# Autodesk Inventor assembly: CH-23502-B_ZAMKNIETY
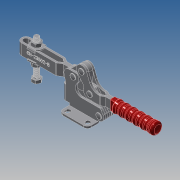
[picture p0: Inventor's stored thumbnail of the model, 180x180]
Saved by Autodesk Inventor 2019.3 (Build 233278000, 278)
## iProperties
Company: ·L?¤¤?
Created: 2010-06
Part Number: CH-23502-B_ZAMKNIETY
Material: Ogólny
Description: STEP AP203
Document SubType Name: Assembly
Designer: CADENGINEERING4
Sending System: SolidWorks 2005179
Preprocessor: SwSTEP 2.0
Title: CH-23502-B.STEP
Author: ·L?¥Î?
Revision Number: ANY
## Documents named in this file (11)
- E:\STRONA\Horizontal toggle clamp\CH-23502-B\CH-23502-B_ZAMKNIETY.iam
- E:\STRONA\Horizontal toggle clamp\CH-23502-B\CH-FC-107512___.ipt
- E:\STRONA\Horizontal toggle clamp\CH-23502-B\23502-B-05___.ipt
- E:\STRONA\Horizontal toggle clamp\CH-23502-B\23502-B-06___.ipt
- E:\STRONA\Horizontal toggle clamp\CH-23502-B\M10___.ipt
- E:\STRONA\Horizontal toggle clamp\CH-23502-B\23502-B-04___.ipt
- E:\STRONA\Horizontal toggle clamp\CH-23502-B\23502-B-07___.ipt
- E:\STRONA\Horizontal toggle clamp\CH-23502-B\23502-B-03___.ipt
- E:\STRONA\Horizontal toggle clamp\CH-23502-B\FW380___.ipt
- E:\STRONA\Horizontal toggle clamp\CH-23502-B\23502-B-02___.ipt
- E:\STRONA\Horizontal toggle clamp\CH-23502-B\23502-B-01___.ipt
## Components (19 placed, 19 different names)
1. CH-FC-107512_??_1 — Zestawiające:5, Zestawiające:7, Równoległe:1, Zestawiające:9, Zestawiające:11, Zestawiające:13
2. 23502-B-05_??_2 — Zestawiające:14, Zestawiające:15
3. 23502-B-06_??_3 — Zestawiające:38, Zestawiające:39
4. M10_??_4 — Zestawiające:11, Zestawiające:12
5. 23502-B-04_??_5 — Zestawiające:22, Zestawiające:23, Zestawiające:24, Zestawiające:25, Zestawiające:26, Zestawiające:34, Kątowe:1
6. 23502-B-05_??_6 — Zestawiające:16, Zestawiające:17, Zestawiające:18
7. M10_??_7 — Zestawiające:7, Zestawiające:8, Równoległe:1
8. 23502-B-07_??_8 — Zestawiające:1, Zestawiające:2, Zestawiające:3
9. 23502-B-05_??_9 — Zestawiające:29, Zestawiające:32, Zestawiające:34
10. 23502-B-04_??_10 — Zestawiające:22, Zestawiające:23, Zestawiające:24, Zestawiające:33
11. 23502-B-03_??_11 — Zestawiające:1, Zestawiające:2, Zestawiające:3, Zestawiające:29, Zestawiające:30, Zestawiające:31, Zestawiające:32, Zestawiające:33, Zestawiające:35, Zestawiające:36, Zestawiające:38, Zestawiające:39
12. 23502-B-06_??_12 — Zestawiające:27, Zestawiające:28
13. FW380_??_13 — Zestawiające:9, Zestawiające:10, Zestawiające:12
14. FW380_??_14 — Zestawiające:4, Zestawiające:5, Zestawiające:6, Zestawiające:8
15. 23502-B-06_??_15 — Zestawiające:20, Zestawiające:21
16. 23502-B-02_??_16 — Zestawiające:4, Zestawiające:6, Zestawiające:10, Zestawiające:13, Zestawiające:18, Zestawiające:19, Zestawiające:37
17. 23502-B-06_??_17 — Zestawiające:35, Zestawiające:36
18. 23502-B-05_??_18 — Zestawiające:30, Zestawiające:31, Zestawiające:37
19. 23502-B-01_??_19 — Zestawiające:14, Zestawiające:15, Zestawiające:16, Zestawiające:17, Zestawiające:19, Zestawiające:20, Zestawiające:21, Zestawiające:25, Zestawiające:26, Zestawiające:27, Zestawiające:28, Kątowe:1
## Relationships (41: Mate 39, Flush 1, Angle 1)
- Zestawiające:1 [Mate]: 23502-B-07_??_8 ↔ 23502-B-03_??_11
- Zestawiające:2 [Mate]: 23502-B-07_??_8 ↔ 23502-B-03_??_11
- Zestawiające:3 [Mate]: 23502-B-07_??_8 ↔ 23502-B-03_??_11
- Zestawiające:4 [Mate]: FW380_??_14 ↔ 23502-B-02_??_16
- Zestawiające:5 [Mate]: CH-FC-107512_??_1 ↔ FW380_??_14
- Zestawiające:6 [Mate]: FW380_??_14 ↔ 23502-B-02_??_16
- Zestawiające:7 [Mate]: CH-FC-107512_??_1 ↔ M10_??_7
- Zestawiające:8 [Mate]: M10_??_7 ↔ FW380_??_14
- Równoległe:1 [Flush]: CH-FC-107512_??_1 ↔ M10_??_7
- Zestawiające:9 [Mate]: CH-FC-107512_??_1 ↔ FW380_??_13
- Zestawiające:10 [Mate]: FW380_??_13 ↔ 23502-B-02_??_16
- Zestawiające:11 [Mate]: CH-FC-107512_??_1 ↔ M10_??_4
- Zestawiające:12 [Mate]: M10_??_4 ↔ FW380_??_13
- Zestawiające:13 [Mate]: CH-FC-107512_??_1 ↔ 23502-B-02_??_16
- Zestawiające:14 [Mate]: 23502-B-05_??_2 ↔ 23502-B-01_??_19
- Zestawiające:15 [Mate]: 23502-B-05_??_2 ↔ 23502-B-01_??_19
- Zestawiające:16 [Mate]: 23502-B-05_??_6 ↔ 23502-B-01_??_19
- Zestawiające:17 [Mate]: 23502-B-05_??_6 ↔ 23502-B-01_??_19
- Zestawiające:18 [Mate]: 23502-B-05_??_6 ↔ 23502-B-02_??_16
- Zestawiające:19 [Mate]: 23502-B-02_??_16 ↔ 23502-B-01_??_19
- Zestawiające:20 [Mate]: 23502-B-06_??_15 ↔ 23502-B-01_??_19
- Zestawiające:21 [Mate]: 23502-B-06_??_15 ↔ 23502-B-01_??_19
- Zestawiające:22 [Mate]: 23502-B-04_??_5 ↔ 23502-B-04_??_10
- Zestawiające:23 [Mate]: 23502-B-04_??_5 ↔ 23502-B-04_??_10
- Zestawiające:24 [Mate]: 23502-B-04_??_5 ↔ 23502-B-04_??_10
- Zestawiające:25 [Mate]: 23502-B-04_??_5 ↔ 23502-B-01_??_19
- Zestawiające:26 [Mate]: 23502-B-04_??_5 ↔ 23502-B-01_??_19
- Zestawiające:27 [Mate]: 23502-B-06_??_12 ↔ 23502-B-01_??_19
- Zestawiające:28 [Mate]: 23502-B-06_??_12 ↔ 23502-B-01_??_19
- Zestawiające:29 [Mate]: 23502-B-05_??_9 ↔ 23502-B-03_??_11
- Zestawiające:30 [Mate]: 23502-B-03_??_11 ↔ 23502-B-05_??_18
- Zestawiające:31 [Mate]: 23502-B-03_??_11 ↔ 23502-B-05_??_18
- Zestawiające:32 [Mate]: 23502-B-05_??_9 ↔ 23502-B-03_??_11
- Zestawiające:33 [Mate]: 23502-B-04_??_10 ↔ 23502-B-03_??_11
- Zestawiające:34 [Mate]: 23502-B-04_??_5 ↔ 23502-B-05_??_9
- Zestawiające:35 [Mate]: 23502-B-03_??_11 ↔ 23502-B-06_??_17
- Zestawiające:36 [Mate]: 23502-B-03_??_11 ↔ 23502-B-06_??_17
- Zestawiające:37 [Mate]: 23502-B-02_??_16 ↔ 23502-B-05_??_18
- Zestawiające:38 [Mate]: 23502-B-06_??_3 ↔ 23502-B-03_??_11
- Zestawiające:39 [Mate]: 23502-B-06_??_3 ↔ 23502-B-03_??_11
- Kątowe:1 [Angle]: 23502-B-04_??_5 ↔ 23502-B-01_??_19
